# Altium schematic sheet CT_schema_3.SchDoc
size 276 x 169 mm
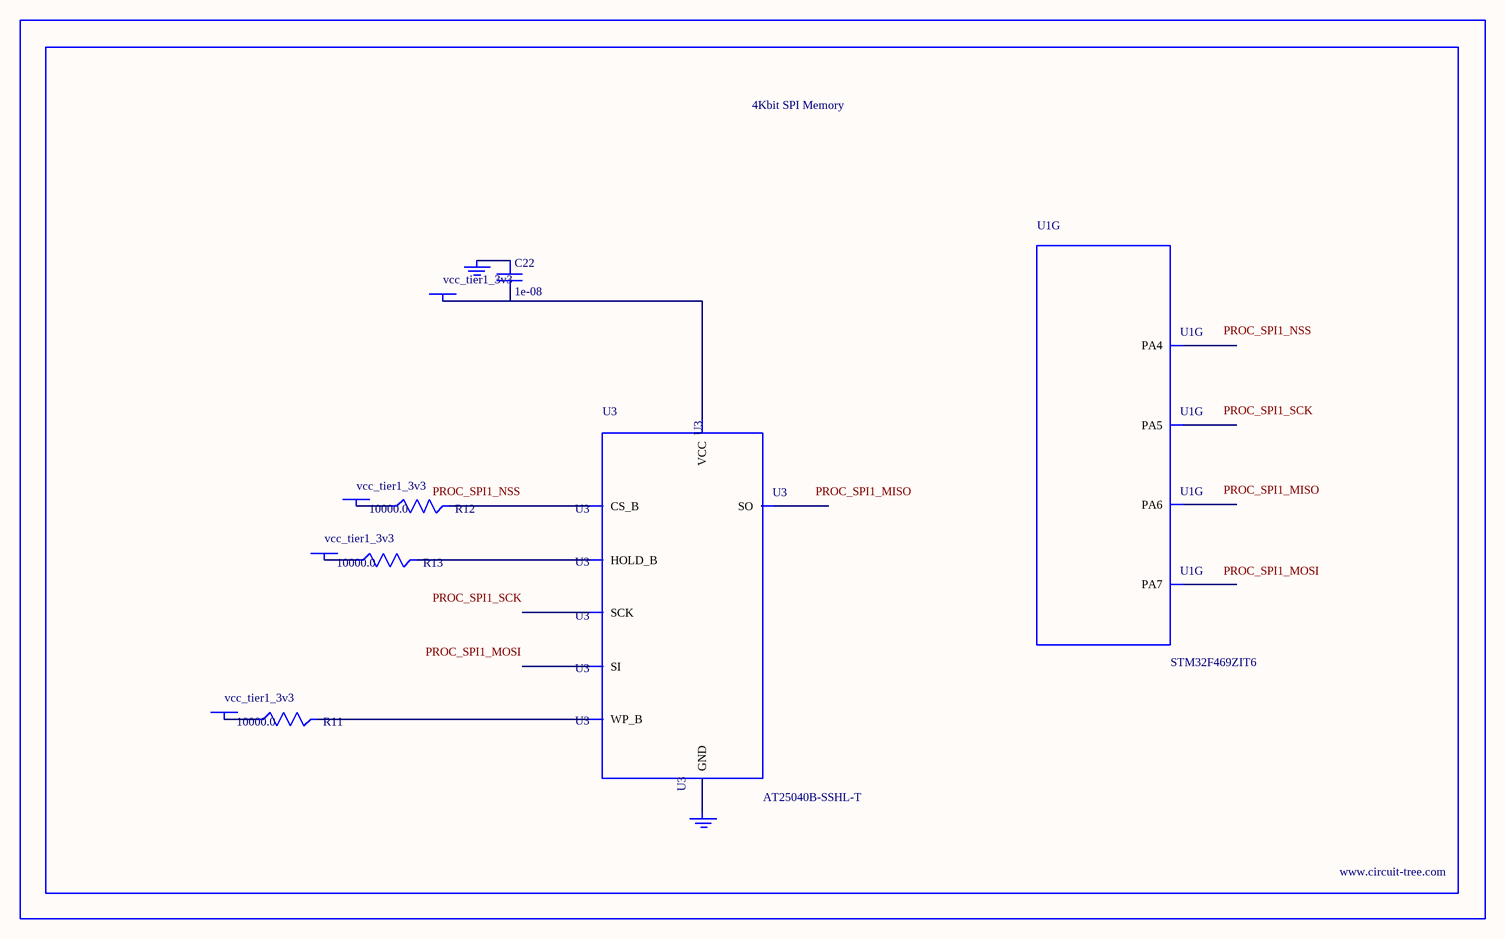
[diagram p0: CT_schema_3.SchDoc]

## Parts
BORDER2  (no value)
C22  1e-08  [C0402]
GND_INSTANCE_2_0  (no value)
GND_INSTANCE_2_1  (no value)
POWER_INSTANCE_2_0  vcc_tier1_3v3
POWER_INSTANCE_2_1  vcc_tier1_3v3
POWER_INSTANCE_2_2  vcc_tier1_3v3
POWER_INSTANCE_2_3  vcc_tier1_3v3
R11  10000.0  [R0603]
R12  10000.0  [R0603]
R13  10000.0  [R0603]
U1  STM32F469ZIT6  [LQFP144]  (part G of 14)
U3  AT25040B-SSHL-T  [SOIC-8]

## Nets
NetC22_1: C22.1 GND_INSTANCE_2_0.0(GND)
NetC22_2: C22.2 POWER_INSTANCE_2_3.0(PWR) U3.8(VCC)
NetGND_INSTANCE_2_1_0: GND_INSTANCE_2_1.0(GND) U3.4(GND)
NetPOWER_INSTANCE_2_0_0: POWER_INSTANCE_2_0.0(PWR) R12.1
NetPOWER_INSTANCE_2_1_0: POWER_INSTANCE_2_1.0(PWR) R11.1
NetPOWER_INSTANCE_2_2_0: POWER_INSTANCE_2_2.0(PWR) R13.1
NetR11_2: R11.2 U3.3(WP_B)
NetR12_2: R12.2 U3.1(CS_B)
NetR13_2: R13.2 U3.7(HOLD_B)

Not connected (* = marked no-connect by the designer): U1 35(PA4) 36(PA5) 37(PA6) 38(PA7); U3 2(SO) 5(SI) 6(SCK)

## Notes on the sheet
- Labels drawn without touching a wire or pin: PROC_SPI1_MISO, PROC_SPI1_MOSI, PROC_SPI1_NSS, PROC_SPI1_SCK

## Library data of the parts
BORDER2 = BORDER_PAGE2
C22 = C0402C103K3RAC
GND_INSTANCE_2_0 GND_INSTANCE_2_1 = GND
POWER_INSTANCE_2_0-POWER_INSTANCE_2_3 = PWR
R11-R13 = RC0603JR-0710KL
